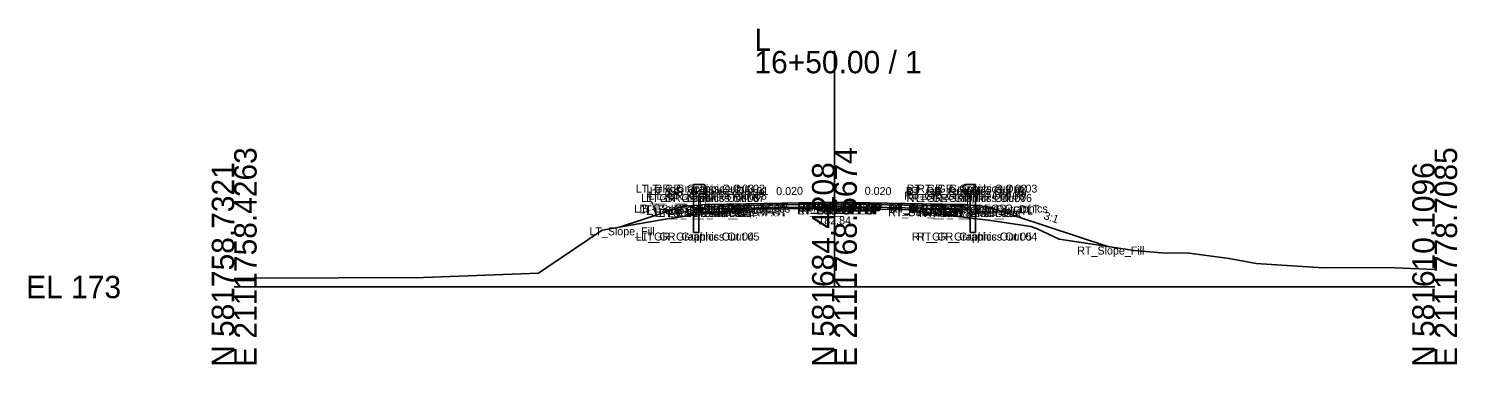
# Model space of a CAD drawing. Extents: x -26 to 3453, y -333 to 9539.
# Drawn here: x -25.7 to 152.8, y 6990.3 to 7032.3 of the extents above; entities that cross this region are included whole.
import ezdxf

# ---------------------------------------------------------------- set-up
doc = ezdxf.new("R2010")
doc.units = 0
for name, color, linetype in [('Default', 7, 'Continuous'), ('Exist Cross Section Cell', 7, 'Continuous'), ('Exist XS Center Line Elevation Label', 7, 'Continuous'), ('Exist XS Ground Line', 7, 'Continuous'), ('Prop CMT Guardrail Graphics', 7, 'Continuous'), ('Prop CMT Pvmt Course 1', 7, 'Continuous'), ('Prop CMT Pvmt Course 2', 7, 'Continuous'), ('Prop CMT Pvmt Course 3', 7, 'Continuous'), ('Prop CMT Pvmt Surface', 7, 'Continuous'), ('Prop CMT Pvmt Surface Shoulder', 7, 'Continuous'), ('Prop CMT Shld Paved Course 1', 7, 'Continuous'), ('Prop CMT Shld Paved Course 2', 7, 'Continuous'), ('Prop CMT Shld Paved Course 3', 7, 'Continuous'), ('Prop CMT Slope Grass', 7, 'Continuous'), ('Prop CMT Subgrade Earthwork', 7, 'Continuous'), ('Prop XS SE Text', 7, 'Continuous'), ('Prop XS Side Slope Text', 7, 'Continuous'), ('Scratch_Level_0', 7, 'Continuous')]:
    doc.layers.add(name, color=color, linetype=linetype)

msp = doc.modelspace()

# ---------------------------------------------------------------- linework, layer by layer
at = {"layer": 'Exist Cross Section Cell'}
for p, q in [((75, 7000), (75, 7029.54)), ((0, 7000), (75, 7000)), ((75, 7000), (150, 7000))]:
    msp.add_line(p, q, dxfattribs=at)
at = {"layer": 'Exist XS Ground Line'}
for p, q in [((57.62, 7009.01), (65.26, 7009.73)), ((65.26, 7009.73), (73.01, 7009.83)), ((73.01, 7009.83), (74.68, 7009.85)), ((74.68, 7009.85), (75, 7009.84)), ((75, 7009.84), (76.36, 7009.81)), ((76.36, 7009.81), (84.28, 7009.66)), ((84.28, 7009.66), (87.61, 7009.15)), ((45.96, 7007.09), (54.35, 7008.57)), ((54.35, 7008.57), (57.62, 7009.01)), ((87.61, 7009.15), (94.54, 7008.33)), ((94.54, 7008.33), (99.54, 7007.59)), ((99.54, 7007.59), (100.26, 7007.33)), ((39.05, 7002.45), (45.96, 7007.09)), ((100.26, 7007.33), (103.09, 7005.99)), ((103.09, 7005.99), (112.44, 7004.56)), ((112.44, 7004.56), (115.86, 7004.28)), ((115.86, 7004.28), (119.34, 7004.22)), ((119.34, 7004.22), (124.34, 7003.55)), ((38.03, 7001.74), (39.05, 7002.45)), ((124.34, 7003.55), (127.68, 7002.96)), ((127.68, 7002.96), (136.07, 7002.38)), ((136.07, 7002.38), (144.07, 7002.42)), ((144.07, 7002.42), (150, 7002.18)), ((0, 7001.07), (0.4, 7001.06)), ((0.4, 7001.06), (2.45, 7001.09)), ((2.45, 7001.09), (23.65, 7001.2)), ((23.65, 7001.2), (25.91, 7001.29)), ((25.91, 7001.29), (38.03, 7001.74))]:
    msp.add_line(p, q, dxfattribs=at)
at = {"layer": 'Prop CMT Guardrail Graphics'}
for points in [[(57.39, 7006.81), (57.39, 7012.81)], [(57.39, 7012.81), (58.72, 7012.81), (58.99, 7012.51)], [(92.61, 7012.81), (91.28, 7012.81), (91.01, 7012.51)], [(92.61, 7006.81), (92.61, 7012.81)], [(58.99, 7011.93), (58.72, 7011.64), (58.05, 7011.64)], [(58.05, 7011.64), (58.05, 7006.81)], [(58.99, 7012.51), (58.72, 7012.22)], [(58.72, 7012.22), (58.99, 7011.93)], [(91.01, 7012.51), (91.28, 7012.22)], [(91.28, 7012.22), (91.01, 7011.93)], [(91.01, 7011.93), (91.28, 7011.64), (91.95, 7011.64)], [(91.95, 7011.64), (91.95, 7006.81)], [(58.05, 7006.81), (57.39, 7006.81)], [(91.95, 7006.81), (92.61, 7006.81)]]:
    msp.add_lwpolyline(points, dxfattribs=at)
at = {"layer": 'Prop CMT Pvmt Course 1'}
for points in [[(75, 7010.63), (64, 7010.41)], [(64, 7010.2), (75, 7010.42)], [(64, 7010.41), (64, 7010.2)], [(75, 7010.42), (75, 7010.63)], [(75, 7010.63), (86, 7010.41)], [(75, 7010.42), (75, 7010.63)], [(86, 7010.2), (75, 7010.42)], [(86, 7010.41), (86, 7010.2)]]:
    msp.add_lwpolyline(points, dxfattribs=at)
msp.add_lwpolyline([(75, 7010.42), (75, 7010.5), (75, 7010.5), (75, 7010.42)], close=True, dxfattribs=at)
msp.add_lwpolyline([(75, 7010.42), (75, 7010.5), (75, 7010.5), (75, 7010.42)], close=True, dxfattribs=at)
at = {"layer": 'Prop CMT Pvmt Course 2'}
for points in [[(75, 7010.42), (64, 7010.2)], [(64, 7010.2), (64, 7009.86)], [(64, 7009.86), (75, 7010.08)], [(75, 7010.08), (75, 7010.42)], [(75, 7010.08), (75, 7010.42)], [(75, 7010.42), (86, 7010.2)], [(86, 7009.86), (75, 7010.08)], [(86, 7010.2), (86, 7009.86)]]:
    msp.add_lwpolyline(points, dxfattribs=at)
at = {"layer": 'Prop CMT Pvmt Course 3'}
for points in [[(75, 7010.08), (64, 7009.86)], [(64, 7009.86), (75, 7010.08)], [(64, 7009.86), (64, 7009.86)], [(75, 7010.08), (75, 7010.08)], [(75, 7010.08), (86, 7009.86)], [(86, 7009.86), (75, 7010.08)], [(75, 7010.08), (75, 7010.08)], [(86, 7009.86), (86, 7009.86)]]:
    msp.add_lwpolyline(points, dxfattribs=at)
at = {"layer": 'Prop CMT Pvmt Surface'}
for points in [[(75, 7010.63), (64, 7010.41)], [(75, 7010.63), (86, 7010.41)]]:
    msp.add_lwpolyline(points, dxfattribs=at)
at = {"layer": 'Prop CMT Pvmt Surface Shoulder'}
for points in [[(64, 7010.41), (59, 7010.31)], [(86, 7010.41), (91, 7010.31)]]:
    msp.add_lwpolyline(points, dxfattribs=at)
at = {"layer": 'Prop CMT Shld Paved Course 1'}
for points in [[(64, 7010.41), (59, 7010.31), (58.79, 7010.09)], [(58.79, 7010.09), (64, 7010.2)], [(64, 7010.2), (64, 7010.41)], [(86, 7010.41), (91, 7010.31), (91.21, 7010.09)], [(86, 7010.2), (86, 7010.41)], [(91.21, 7010.09), (86, 7010.2)]]:
    msp.add_lwpolyline(points, dxfattribs=at)
at = {"layer": 'Prop CMT Shld Paved Course 2'}
for points in [[(64, 7010.2), (58.79, 7010.09), (58.45, 7009.75)], [(58.45, 7009.75), (64, 7009.86)], [(64, 7009.86), (64, 7010.2)], [(86, 7010.2), (91.21, 7010.09), (91.55, 7009.75)], [(86, 7009.86), (86, 7010.2)], [(91.55, 7009.75), (86, 7009.86)]]:
    msp.add_lwpolyline(points, dxfattribs=at)
at = {"layer": 'Prop CMT Shld Paved Course 3'}
for points in [[(64, 7009.86), (58.45, 7009.75)], [(58.45, 7009.75), (64, 7009.86)], [(58.45, 7009.75), (58.45, 7009.75), (58.45, 7009.75)], [(64, 7009.86), (64, 7009.86)], [(86, 7009.86), (91.55, 7009.75)], [(91.55, 7009.75), (86, 7009.86)], [(86, 7009.86), (86, 7009.86)], [(91.55, 7009.75), (91.55, 7009.75), (91.55, 7009.75)]]:
    msp.add_lwpolyline(points, dxfattribs=at)
at = {"layer": 'Prop CMT Slope Grass'}
for points in [[(56, 7010.07), (48.13, 7007.47)], [(58.99, 7010.31), (56, 7010.07)], [(59, 7010.31), (58.99, 7010.31)], [(91, 7010.31), (91.01, 7010.31)], [(91.01, 7010.31), (94, 7010.07)], [(94, 7010.07), (109.16, 7005.06)]]:
    msp.add_lwpolyline(points, dxfattribs=at)
at = {"layer": 'Prop CMT Subgrade Earthwork'}
for points in [[(58.45, 7009.75), (57.98, 7010.22)], [(64, 7009.86), (58.45, 7009.75)], [(75, 7010.08), (64, 7009.86)], [(75, 7010.08), (86, 7009.86)], [(86, 7009.86), (91.55, 7009.75)], [(91.55, 7009.75), (92.02, 7010.22)]]:
    msp.add_lwpolyline(points, dxfattribs=at)

# ---------------------------------------------------------------- texts
at = {"layer": 'Default'}
msp.add_text('-', height=0.0001, dxfattribs=at).set_placement((0, 7000))
at = {"layer": 'Exist Cross Section Cell'}
for s, p in [('L', (65, 7029.54)), ('16+50.00 / 1', (65, 7026.74)), ('EL 173', (-26, 6998.6))]:
    msp.add_text(s, height=2.8, dxfattribs=at).set_placement(p)
for s, p in [('E 2111758.4263', (2.8, 6990)), ('E 2111768.5674', (77.8, 6990)), ('E 2111778.7085', (152.8, 6990)), ('N 581758.7321', (0, 6990)), ('N 581684.4208', (75, 6990)), ('N 581610.1096', (150, 6990))]:
    msp.add_text(s, height=2.8, rotation=90, dxfattribs=at).set_placement(p)
at = {"layer": 'Exist XS Center Line Elevation Label'}
msp.add_text('182.84', height=1, dxfattribs=at).set_placement((72.98, 7007.84))
at = {"layer": 'Prop XS SE Text'}
for rotation, p in [(1.1458, (67.73, 7011.48)), (358.8542, (78.77, 7011.55))]:
    msp.add_text('0.020', height=1, rotation=rotation, dxfattribs=at).set_placement(p)
at = {"layer": 'Prop XS Side Slope Text'}
for rotation, p in [(18.2629, (51.08, 7009.23)), (341.7371, (101.06, 7008.52))]:
    msp.add_text('3:1', height=1, rotation=rotation, dxfattribs=at).set_placement(p)
at = {"layer": 'Scratch_Level_0'}
for s, p in [('LT_GR_Graphics Out 03', (50.17, 7011.81)), ('LT_GR_Graphics Out 02', (51.52, 7011.81)), ('RT_GR_Graphics Out 02', (84.02, 7011.81)), ('RT_GR_Graphics Out 03', (85.34, 7011.81)), ('LT_GR_Graphics Out 06', (50.83, 7010.64)), ('LT_GR_Graphics Out 07', (51.48, 7010.64)), ('LT_GR_Graphics Out 09', (51.49, 7011.22)), ('LT_GR_Graphics Out 08', (51.76, 7010.93)), ('LT_GR_Graphics Out 01', (51.94, 7011.51)), ('RT_GR_Graphics Out 08', (83.72, 7010.93)), ('RT_GR_Graphics Out 01', (83.9, 7011.51)), ('RT_GR_Graphics Out 07', (83.98, 7010.64)), ('RT_GR_Graphics Out 09', (84, 7011.22)), ('RT_GR_Graphics Out 06', (84.66, 7010.64)), ('LT_GS_OS_GR_Face_Graphics', (49.99, 7009.31)), ('LT_Sub_Trench_Out_DLT', (50.63, 7009.22)), ('LT_GS_OS_CTL', (51.46, 7009.07)), ('LT_Sub_Trench_Out', (52.56, 7008.75)), ('LT_PS3_Shelf_Out', (53.1, 7008.75)), ('LT_PS3_OEOP', (54.23, 7008.75)), ('LT_PS2_OEOP', (54.57, 7009.09)), ('LT_PS1_OEOP', (54.91, 7009.31)), ('LT_PV2_OEOT', (59.75, 7009.2)), ('LT_PV3_OEOT', (59.75, 7008.86)), ('LT_Sub_OEOT', (59.77, 7008.86)), ('LT_PV1_OEOT', (59.87, 7009.41)), ('RT_PV2_OEEOP', (70.33, 7009.42)), ('RT_PV3_OEEOP', (70.33, 7009.08)), ('RT_Sub_OEEOP', (70.36, 7009.08)), ('LT_PV2_OEEOP', (70.39, 7009.42)), ('LT_PV3_OEEOP', (70.39, 7009.08)), ('LT_Sub_OEEOP', (70.42, 7009.08)), ('RT_PV1_OEEOP', (70.45, 7009.5)), ('LT_PV1_OEEOP', (70.51, 7009.5)), ('RT_PV2_IEEOP', (70.71, 7009.42)), ('LT_PV2_IEEOP', (70.77, 7009.42)), ('RT_PV1_IEEOP', (70.83, 7009.5)), ('LT_PV1_IEEOP', (70.89, 7009.5)), ('PV2_PGL', (72.35, 7009.42)), ('PV1_PGL', (72.47, 7009.63)), ('RT_PV2_OEOT', (81.69, 7009.2)), ('RT_PV3_OEOT', (81.69, 7008.86)), ('RT_Sub_OEOT', (81.71, 7008.86)), ('RT_PV1_OEOT', (81.81, 7009.41)), ('RT_GS_OS_GR_Face_Graphics', (81.95, 7009.31)), ('RT_Sub_Trench_Out_DLT', (84.61, 7009.22)), ('RT_Sub_Trench_Out', (85.6, 7008.75)), ('RT_PS3_Shelf_Out', (86.15, 7008.75)), ('RT_PS1_OEOP', (86.85, 7009.31)), ('RT_PS2_OEOP', (86.94, 7009.09)), ('RT_PS3_OEOP', (87.28, 7008.75)), ('RT_GS_OS_CTL', (89.4, 7009.07)), ('LT_Slope_Fill', (44.37, 7006.47)), ('LT_GR_Graphics Out 04', (50.16, 7005.81)), ('LT_GR_Graphics Out 05', (50.83, 7005.81)), ('RT_GR_Graphics Out 05', (84.67, 7005.81)), ('RT_GR_Graphics Out 04', (85.32, 7005.81)), ('RT_Slope_Fill', (105.34, 7004.06))]:
    msp.add_text(s, height=1, dxfattribs=at).set_placement(p)

doc.saveas('drawing.dxf')
